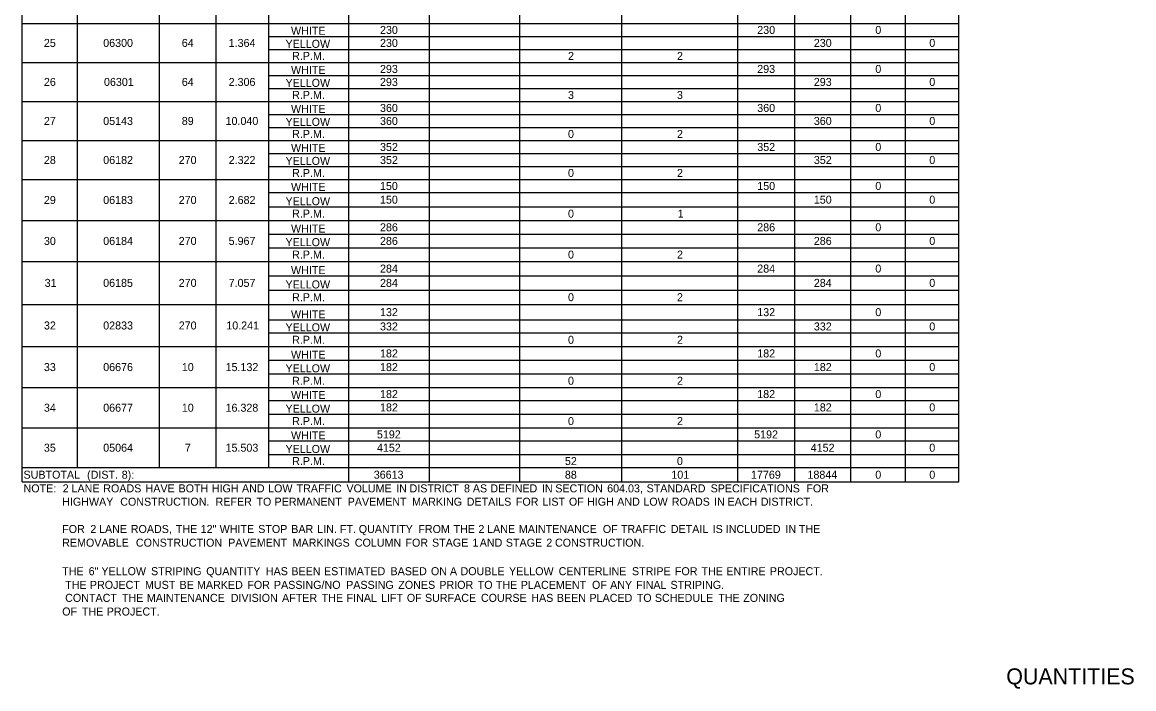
# Model space of a CAD drawing. Extents: x 544420 to 1930787, y -1947044 to 596640.
# Drawn here: x 548756 to 549589, y -1947044 to -1946545 of the extents above; entities that cross this region are included whole.
import ezdxf

# ---------------------------------------------------------------- set-up
doc = ezdxf.new("R2010")
doc.units = 0
doc.layers.add('Default', color=7, linetype='Continuous')
doc.layers.add('R_Annotation', color=7, linetype='Continuous')

msp = doc.modelspace()

# ---------------------------------------------------------------- linework, layer by layer
at = {"layer": 'Default'}
for p, q in [((548755.58, -1946889.12), (548755.58, -1946119.36)), ((548797.01, -1946878.4), (548797.01, -1946119.36)), ((548858.44, -1946878.4), (548858.44, -1946119.36)), ((548900.85, -1946878.4), (548900.85, -1946119.36)), ((548940.34, -1946878.4), (548940.34, -1946119.36)), ((549000.3, -1946889.12), (549000.3, -1946119.36)), ((549060.75, -1946889.12), (549060.75, -1946119.36)), ((549128.51, -1946889.12), (549128.51, -1946119.36)), ((549291.83, -1946889.12), (549291.83, -1946119.36)), ((549376.65, -1946889.12), (549376.65, -1946119.36)), ((549457.58, -1946889.12), (549457.58, -1946119.36)), ((549205.05, -1946889.12), (549205.05, -1946187.61)), ((549334.73, -1946889.12), (549334.73, -1946187.61)), ((549417.6, -1946889.12), (549417.6, -1946187.61)), ((548755.58, -1946545.44), (549457.58, -1946545.44)), ((548940.34, -1946555.19), (549457.58, -1946555.19)), ((548940.34, -1946564.94), (549457.58, -1946564.94)), ((548755.58, -1946574.69), (549457.58, -1946574.69)), ((548940.34, -1946584.44), (549457.58, -1946584.44)), ((548940.34, -1946594.19), (549457.58, -1946594.19)), ((548755.58, -1946603.94), (549457.58, -1946603.94)), ((548940.34, -1946613.69), (549457.58, -1946613.69)), ((548940.34, -1946623.44), (549457.58, -1946623.44)), ((548755.58, -1946633.19), (549457.58, -1946633.19)), ((548940.34, -1946642.94), (549457.58, -1946642.94)), ((548940.34, -1946652.69), (549457.58, -1946652.69)), ((548755.58, -1946662.44), (549457.58, -1946662.44)), ((548940.34, -1946672.19), (549457.58, -1946672.19)), ((548940.34, -1946682.91), (549457.58, -1946682.91)), ((548755.58, -1946693.15), (549457.58, -1946693.15)), ((548940.34, -1946703.39), (549457.58, -1946703.39)), ((548940.34, -1946713.62), (549457.58, -1946713.62)), ((548755.58, -1946723.86), (549457.58, -1946723.86)), ((548940.34, -1946734.59), (549457.58, -1946734.59)), ((548940.34, -1946745.31), (549457.58, -1946745.31)), ((548755.58, -1946756.04), (549457.58, -1946756.04)), ((548940.34, -1946767.74), (549457.58, -1946767.74)), ((548940.34, -1946777.49), (549457.58, -1946777.49)), ((548755.58, -1946787.72), (549457.58, -1946787.72)), ((548940.34, -1946797.96), (549457.58, -1946797.96)), ((548940.34, -1946808.2), (549457.58, -1946808.2)), ((548755.58, -1946818.44), (549457.58, -1946818.44)), ((548940.34, -1946828.19), (549457.58, -1946828.19)), ((548940.34, -1946838.42), (549457.58, -1946838.42)), ((548755.58, -1946848.66), (549457.58, -1946848.66)), ((548940.34, -1946858.41), (549457.58, -1946858.41)), ((548940.34, -1946868.65), (549457.58, -1946868.65)), ((548755.58, -1946878.4), (549457.58, -1946878.4)), ((549000.3, -1946889.12), (549000.3, -1946878.4)), ((549060.75, -1946889.12), (549060.75, -1946878.4)), ((549128.51, -1946889.12), (549128.51, -1946878.4)), ((549205.05, -1946889.12), (549205.05, -1946878.4)), ((549291.83, -1946889.12), (549291.83, -1946878.4)), ((549334.73, -1946889.12), (549334.73, -1946878.4)), ((549376.65, -1946889.12), (549376.65, -1946878.4)), ((549417.6, -1946889.12), (549417.6, -1946878.4)), ((548755.58, -1946889.12), (549457.58, -1946889.12))]:
    msp.add_line(p, q, dxfattribs=at)

# ---------------------------------------------------------------- texts
for s, p in [('230', (549023.74, -1946553.31)), ('230', (549306.49, -1946553.31)), ('0', (549395, -1946553.31)), ('WHITE', (548957.04, -1946553.99)), ('25', (548771.8, -1946563.06)), ('06300', (548816.28, -1946563.06)), ('64', (548875.19, -1946563.06)), ('1.364', (548910.32, -1946563.06)), ('YELLOW', (548952.9, -1946563.74)), ('230', (549023.74, -1946563.06)), ('230', (549348.9, -1946563.06)), ('0', (549435.46, -1946563.06)), ('R.P.M.', (548957.88, -1946572.81)), ('2', (549164.68, -1946572.81)), ('2', (549246.33, -1946572.81)), ('WHITE', (548957.04, -1946583.24)), ('293', (549023.73, -1946582.56)), ('293', (549306.48, -1946582.56)), ('0', (549395, -1946582.56)), ('26', (548771.83, -1946592.31)), ('06301', (548816.85, -1946592.31)), ('64', (548875.19, -1946592.31)), ('2.306', (548910.3, -1946592.31)), ('YELLOW', (548952.9, -1946592.99)), ('293', (549023.73, -1946592.31)), ('293', (549348.89, -1946592.31)), ('0', (549435.46, -1946592.31)), ('R.P.M.', (548957.88, -1946602.06)), ('3', (549164.64, -1946602.06)), ('3', (549246.3, -1946602.06)), ('360', (549023.74, -1946611.81)), ('360', (549306.49, -1946611.81)), ('0', (549395, -1946611.81)), ('WHITE', (548957.04, -1946612.49)), ('27', (548771.83, -1946621.56)), ('05143', (548816.27, -1946621.56)), ('89', (548875.17, -1946621.56)), ('10.040', (548907.98, -1946621.56)), ('YELLOW', (548952.9, -1946622.24)), ('360', (549023.74, -1946621.56)), ('360', (549348.9, -1946621.56)), ('0', (549435.46, -1946621.56)), ('R.P.M.', (548957.88, -1946631.31)), ('0', (549164.65, -1946631.31)), ('2', (549246.33, -1946631.31)), ('WHITE', (548957.04, -1946641.74)), ('352', (549023.76, -1946641.06)), ('352', (549306.51, -1946641.06)), ('0', (549395, -1946641.06)), ('28', (548771.82, -1946650.81)), ('06182', (548816.3, -1946650.81)), ('270', (548872.86, -1946650.81)), ('2.322', (548910.33, -1946650.81)), ('YELLOW', (548952.9, -1946651.49)), ('352', (549023.76, -1946650.81)), ('352', (549348.92, -1946650.81)), ('0', (549435.46, -1946650.81)), ('R.P.M.', (548957.88, -1946660.56)), ('0', (549164.65, -1946660.56)), ('2', (549246.33, -1946660.56)), ('150', (549023.74, -1946670.31)), ('150', (549306.49, -1946670.31)), ('0', (549395, -1946670.31)), ('WHITE', (548957.04, -1946670.99)), ('29', (548771.82, -1946680.79)), ('06183', (548816.27, -1946680.79)), ('270', (548872.86, -1946680.79)), ('2.682', (548910.33, -1946680.79)), ('YELLOW', (548952.9, -1946681.71)), ('150', (549023.74, -1946680.55)), ('150', (549348.9, -1946680.55)), ('0', (549435.46, -1946680.55)), ('R.P.M.', (548957.88, -1946691.03)), ('0', (549164.65, -1946691.03)), ('1', (549246.88, -1946691.03)), ('WHITE', (548957.04, -1946702.19)), ('286', (549023.73, -1946701.27)), ('286', (549306.48, -1946701.27)), ('0', (549395, -1946701.27)), ('30', (548771.84, -1946711.5)), ('06184', (548816.28, -1946711.5)), ('270', (548872.86, -1946711.5)), ('5.967', (548910.3, -1946711.5)), ('286', (549023.73, -1946711.5)), ('286', (549348.89, -1946711.5)), ('0', (549435.46, -1946711.5)), ('YELLOW', (548952.9, -1946712.42)), ('R.P.M.', (548957.88, -1946721.74)), ('0', (549164.65, -1946721.74)), ('2', (549246.33, -1946721.74)), ('WHITE', (548957.04, -1946733.39)), ('284', (549023.74, -1946732.22)), ('284', (549306.49, -1946732.22)), ('0', (549395, -1946732.22)), ('31', (548772.41, -1946742.95)), ('06185', (548816.24, -1946742.95)), ('270', (548872.86, -1946742.95)), ('7.057', (548910.3, -1946742.95)), ('YELLOW', (548952.9, -1946744.11)), ('284', (549023.74, -1946742.95)), ('284', (549348.9, -1946742.95)), ('0', (549435.46, -1946742.95)), ('R.P.M.', (548957.88, -1946753.67)), ('0', (549164.65, -1946753.67)), ('2', (549246.33, -1946753.67)), ('WHITE', (548957.04, -1946766.54)), ('132', (549023.76, -1946764.89)), ('132', (549306.51, -1946764.89)), ('0', (549395, -1946764.89)), ('32', (548771.86, -1946774.88)), ('02833', (548816.27, -1946774.88)), ('270', (548872.86, -1946774.88)), ('10.241', (548908.55, -1946774.88)), ('YELLOW', (548952.9, -1946776.29)), ('332', (549023.76, -1946775.61)), ('332', (549348.92, -1946775.61)), ('0', (549435.46, -1946775.61)), ('R.P.M.', (548957.88, -1946785.6)), ('0', (549164.65, -1946785.6)), ('2', (549246.33, -1946785.6)), ('WHITE', (548957.04, -1946796.76)), ('182', (549023.76, -1946795.84)), ('182', (549306.51, -1946795.84)), ('0', (549395, -1946795.84)), ('33', (548771.83, -1946806.08)), ('06676', (548816.27, -1946806.08)), ('10', (548875.19, -1946806.08)), ('15.132', (548908, -1946806.08)), ('YELLOW', (548952.9, -1946807)), ('182', (549023.76, -1946806.08)), ('182', (549348.92, -1946806.08)), ('0', (549435.46, -1946806.08)), ('R.P.M.', (548957.88, -1946816.32)), ('0', (549164.65, -1946816.32)), ('2', (549246.33, -1946816.32)), ('WHITE', (548957.04, -1946826.99)), ('182', (549023.76, -1946826.31)), ('182', (549306.51, -1946826.31)), ('0', (549395, -1946826.31)), ('34', (548771.84, -1946836.55)), ('06677', (548816.27, -1946836.55)), ('10', (548875.19, -1946836.55)), ('16.328', (548907.97, -1946836.55)), ('182', (549023.76, -1946836.3)), ('182', (549348.92, -1946836.3)), ('0', (549435.46, -1946836.3)), ('YELLOW', (548952.9, -1946837.22)), ('R.P.M.', (548957.88, -1946846.54)), ('0', (549164.65, -1946846.54)), ('2', (549246.33, -1946846.54)), ('WHITE', (548957.04, -1946857.21)), ('5192', (549021.43, -1946856.54)), ('5192', (549304.18, -1946856.54)), ('0', (549395, -1946856.54)), ('35', (548771.8, -1946866.53)), ('05064', (548816.28, -1946866.53)), ('7', (548877.51, -1946866.53)), ('15.503', (548907.97, -1946866.53)), ('YELLOW', (548952.9, -1946867.45)), ('4152', (549021.43, -1946866.53)), ('4152', (549346.59, -1946866.53)), ('0', (549435.46, -1946866.53)), ('R.P.M.', (548957.88, -1946876.52)), ('52', (549162.35, -1946876.52)), ('0', (549246.31, -1946876.52)), ('SUBTOTAL', (548756.55, -1946886.76)), (' (DIST.', (548801.95, -1946886.76)), (' 8):', (548827.91, -1946886.76)), ('36613', (549019.06, -1946886.76)), ('88', (549162.31, -1946886.76)), ('101', (549242.13, -1946886.76)), ('17769', (549301.82, -1946886.76)), ('18844', (549344.14, -1946886.76)), ('0', (549395, -1946886.76)), ('0', (549435.47, -1946886.76)), ('NOTE:', (548756.55, -1946897)), ('  2', (548781.44, -1946897)), (' LANE', (548790.31, -1946897)), (' ROADS', (548814.09, -1946897)), (' HAVE', (548845.8, -1946897)), (' BOTH', (548870.51, -1946897)), (' HIGH', (548895.45, -1946897)), (' AND', (548918.06, -1946897)), (' LOW', (548937.65, -1946897)), (' TRAFFIC', (548958.97, -1946897)), (' VOLUME', (548996.36, -1946897)), (' IN', (549033.65, -1946897)), (' DISTRICT', (549043.67, -1946897)), (' 8', (549084.48, -1946897)), (' AS', (549091.1, -1946897)), (' DEFINED', (549104.18, -1946897)), (' IN', (549142.86, -1946897)), (' SECTION', (549152.88, -1946897)), (' 604.03,', (549191.79, -1946897)), (' STANDARD', (549221.33, -1946897)), (' SPECIFICATIONS', (549269.33, -1946897)), (' FOR', (549341.09, -1946897)), ('             HIGHWAY', (548756.55, -1946906.99)), (' CONSTRUCTION.', (548826.81, -1946906.99)), (' REFER', (548898.27, -1946906.99)), (' TO', (548928.9, -1946906.99)), (' PERMANENT', (548942.49, -1946906.99)), (' PAVEMENT', (548997.29, -1946906.99)), (' MARKING', (549045.58, -1946906.99)), (' DETAILS', (549086.51, -1946906.99)), (' FOR', (549123.34, -1946906.99)), (' LIST', (549143.25, -1946906.99)), (' OF', (549163.11, -1946906.99)), (' HIGH', (549176.7, -1946906.99)), (' AND', (549199.31, -1946906.99)), (' LOW', (549218.89, -1946906.99)), (' ROADS', (549240.22, -1946906.99)), (' IN', (549271.92, -1946906.99)), (' EACH', (549281.95, -1946906.99)), (' DISTRICT.', (549306.89, -1946906.99)), ('             FOR', (548756.55, -1946927.47)), (' 2', (548804.4, -1946927.47)), (' LANE', (548810.94, -1946927.47)), (' ROADS,', (548834.72, -1946927.47)), (' THE', (548868.45, -1946927.47)), (' 12"', (548887.1, -1946927.47)), (' WHITE', (548901.33, -1946927.47)), (' STOP', (548930.22, -1946927.47)), (' BAR', (548955.01, -1946927.47)), (' LIN.', (548974.46, -1946927.47)), (' FT.', (548991.43, -1946927.47)), (' QUANTITY', (549005.6, -1946927.47)), (' FROM', (549050.25, -1946927.47)), (' THE', (549076.63, -1946927.47)), (' 2', (549095.28, -1946927.47)), (' LANE', (549101.82, -1946927.47)), (' MAINTENANCE', (549125.6, -1946927.47)), (' OF', (549188.51, -1946927.47)), (' TRAFFIC', (549202.09, -1946927.47)), (' DETAIL', (549239.48, -1946927.47)), (' IS', (549270.86, -1946927.47)), (' INCLUDED', (549280.67, -1946927.47)), (' IN', (549325.41, -1946927.47)), (' THE', (549335.43, -1946927.47)), ('             REMOVABLE', (548756.55, -1946937.7)), (' CONSTRUCTION', (548838.55, -1946937.7)), (' PAVEMENT', (548907.73, -1946937.7)), (' MARKINGS', (548956.01, -1946937.7)), (' COLUMN', (549002.62, -1946937.7)), (' FOR', (549040.59, -1946937.7)), (' STAGE', (549060.5, -1946937.7)), (' 1', (549090.81, -1946937.7)), (' AND', (549096.25, -1946937.7)), (' STAGE', (549115.83, -1946937.7)), (' 2', (549146.14, -1946937.7)), (' CONSTRUCTION.', (549152.68, -1946937.7)), ('             THE', (548756.55, -1946959.1)), (' 6"', (548803.13, -1946959.1)), (' YELLOW', (548812.71, -1946959.1)), (' STRIPING', (548849.88, -1946959.1)), (' QUANTITY', (548891.27, -1946959.1)), (' HAS', (548935.93, -1946959.1)), (' BEEN', (548955.06, -1946959.1)), (' ESTIMATED', (548979.53, -1946959.1)), (' BASED', (549029.39, -1946959.1)), (' ON', (549059.7, -1946959.1)), (' A', (549073.92, -1946959.1)), (' DOUBLE', (549081.85, -1946959.1)), (' YELLOW', (549118.21, -1946959.1)), (' CENTERLINE', (549155.38, -1946959.1)), (' STRIPE', (549210.37, -1946959.1)), (' FOR', (549242.53, -1946959.1)), (' THE', (549262.44, -1946959.1)), (' ENTIRE', (549281.09, -1946959.1)), (' PROJECT.', (549313.72, -1946959.1)), ('THE', (548787.75, -1946969.34)), (' PROJECT', (548804.07, -1946969.34)), (' MUST', (548845.36, -1946969.34)), (' BE', (548871.28, -1946969.34)), (' MARKED', (548884.34, -1946969.34)), (' FOR', (548922.09, -1946969.34)), (' PASSING/NO', (548942.01, -1946969.34)), (' PASSING', (548996.14, -1946969.34)), (' ZONES', (549035.22, -1946969.34)), (' PRIOR', (549065.99, -1946969.34)), (' TO', (549094.75, -1946969.34)), (' THE', (549108.35, -1946969.34)), (' PLACEMENT', (549127, -1946969.34)), (' OF', (549180.4, -1946969.34)), (' ANY', (549193.99, -1946969.34)), (' FINAL', (549213.5, -1946969.34)), (' STRIPING.', (549239.28, -1946969.34)), ('CONTACT', (548787.75, -1946979.09)), (' THE', (548828.11, -1946979.09)), (' MAINTENANCE', (548846.76, -1946979.09)), (' DIVISION', (548909.66, -1946979.09)), (' AFTER', (548948.1, -1946979.09)), (' THE', (548977.8, -1946979.09)), (' FINAL', (548996.45, -1946979.09)), (' LIFT', (549022.24, -1946979.09)), (' OF', (549041.63, -1946979.09)), (' SURFACE', (549055.21, -1946979.09)), (' COURSE', (549097.16, -1946979.09)), (' HAS', (549134.91, -1946979.09)), (' BEEN', (549154.04, -1946979.09)), (' PLACED', (549178.52, -1946979.09)), (' TO', (549213.94, -1946979.09)), (' SCHEDULE', (549227.54, -1946979.09)), (' THE', (549275.08, -1946979.09)), (' ZONING', (549293.73, -1946979.09)), ('             OF', (548756.55, -1946989.32)), (' THE', (548798.07, -1946989.32)), (' PROJECT.', (548816.72, -1946989.32))]:
    msp.add_text(s, height=6, dxfattribs=at).set_placement(p)
at = {"layer": 'R_Annotation'}
msp.add_text('QUANTITIES', height=12, rotation=360, dxfattribs=at).set_placement((549493.16, -1947040.95))

doc.saveas('drawing.dxf')
